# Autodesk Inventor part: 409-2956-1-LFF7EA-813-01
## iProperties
Created: 2010-11
Part Number: 409-2956-1-LFF7EA-813-01
Material: 3/8" OD TUBE - SS
Description: PT TUBING
Document SubType Name: Modeling
Designer: S. Boerckel
Engineer: Steve Boerckel
Mass: 769.029 g
Surface Area: 1665.99 cm^2
Volume: 95.1769 cm^3
Density: 8.08 g/cm^3
Length: 140.315 in
Author: S. Boerckel
Revision Number: 0
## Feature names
1. Sweep1
